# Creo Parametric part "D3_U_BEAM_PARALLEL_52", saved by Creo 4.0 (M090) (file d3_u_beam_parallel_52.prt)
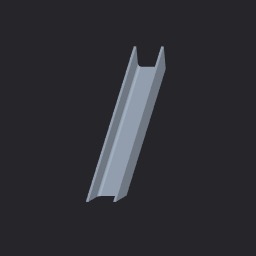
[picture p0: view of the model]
Units: Custom; MM, KILOGRAM, SECS
Materials in the file: STEEL

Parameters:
  BUW_NAME = "U BEAM"
  BUW_SIZE = "UPE 100"
  BUW_LENGTH_STR = "610.2"
  PTC_MATERIAL_NAME = "STEEL"
  BUW_PROFIL_TYPE = "u_beam_parallel"
  BUW_PROFILE_PATH = "parts/profiles/steel_beams_mm/"
  BUW_PROFILE_NAME_LANG = "CHANNEL BEAM PARALLEL"
  BUW_TAB_SEL_INFO = "2  0 0  1 1"
  MITRE_SYM_X_S = "/"
  MITRE_SYM_X_E = "\"
  MITRE_SYM_X = "/---\"
  MITRE_BOM_X = "X /---\"
  MITRE_SYM_Y_S = "|"
  MITRE_SYM_Y_E = "|"
  MITRE_SYM_Y = "|---|"
  BUW_DOUBLE_TO_STR_INFO = "X_ROT_S2 2 X_ROT_E2 2 Y_ROT_S2 2 Y_ROT_E2 2"
  X_ROT_S2_STR = "51.34"
  X_ROT_E2_STR = "38.66"
  Y_ROT_S2_STR = "90"
  Y_ROT_E2_STR = "90"
  BOM_ANGLE_S = "X 51.34°"
  BOM_ANGLE_E = "X 38.66°"
  EFX_ITEM_NR = "5"
  PROFIL_RASTER_POS = "X_0"
  BUW_OBJECT_ROLE = "PROFILE_SYSTEM_BORE_END_POINTS"
  PRO_UNIT_SYS = "Custom"

Other parameters: BUW_LENGTH, SEC_CENTER_OFF_Y, X_ROT_S2, X_ROT_E2, Y_ROT_S2, Y_ROT_E2, D8, d26, d8, d103, D103, D0, D4, D1, D5, SHEAR_MODULUS, THERM_EXPANSION_REF_TEMPERATURE, STRUCTURAL_DAMPING_COEFFICIENT, STRESS_LIMIT_FOR_TENSION, STRESS_LIMIT_FOR_COMPRESSION, STRESS_LIMIT_FOR_SHEAR, EMISSIVITY

Created from: U_BEAM_PARALLEL.PRT

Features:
  1. datum plane "YZ"
  2. datum plane "XZ"
  3. datum plane "XY"
  4. coordinate system
  5. coordinate system
  6. coordinate system
  7. coordinate system
  8. datum plane "DTM3"
  9. datum plane "DTM4"
  10. datum plane "DTM5"
  11. protrusion
  12. datum plane "DTM6"
  13. feature "PNT_XSEC_COG"
  14. datum axis
  15. datum axis
  16. datum point "PNT0"
  17. datum point

Other named items: PROFIL_CUT_QUILT, PROFILE_LENGTH_DIM, CG_ANALYSIS, CONTACT_SURF_3, CONTACT_SURF_2, CONTACT_SURF_1, CONTACT_SURF_0, E, START_SURFACE, END_SURFACE, SIDE_SURF_7, SIDE_SURF_5, SIDE_SURF_4, SIDE_SURF_3, SIDE_SURF_2, SIDE_SURF_1, EDGE_11_S, EDGE_10_S, EDGE_9_S, EDGE_11_E, EDGE_10_E, EDGE_9_E, EDGE_5_S, EDGE_4_S, EDGE_3_S, EDGE_5_E, EDGE_4_E, EDGE_3_E, CG, CS0, CS_S, CS_E, CS3

Named dimensions: X_ROT_S, Y_ROT_S, Z_OFF_S, X_ROT_E, Y_ROT_E, Z_OFF_E, PC_L, BUW_LENGTH_Z_MIN, BUW_LENGTH_DIM

Layers: 00_PROFIL_CG, 00_PROFIL_DATUM, 00_PROFIL_DRW_HIDE, 00_PROFIL_END_CSYS, 00_PROFIL_GEOMETRY, 00_PROFIL_QUILT, 00_PROFIL_SIZE_NOTE

Surfaces: 10 plane, 2 cylinder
